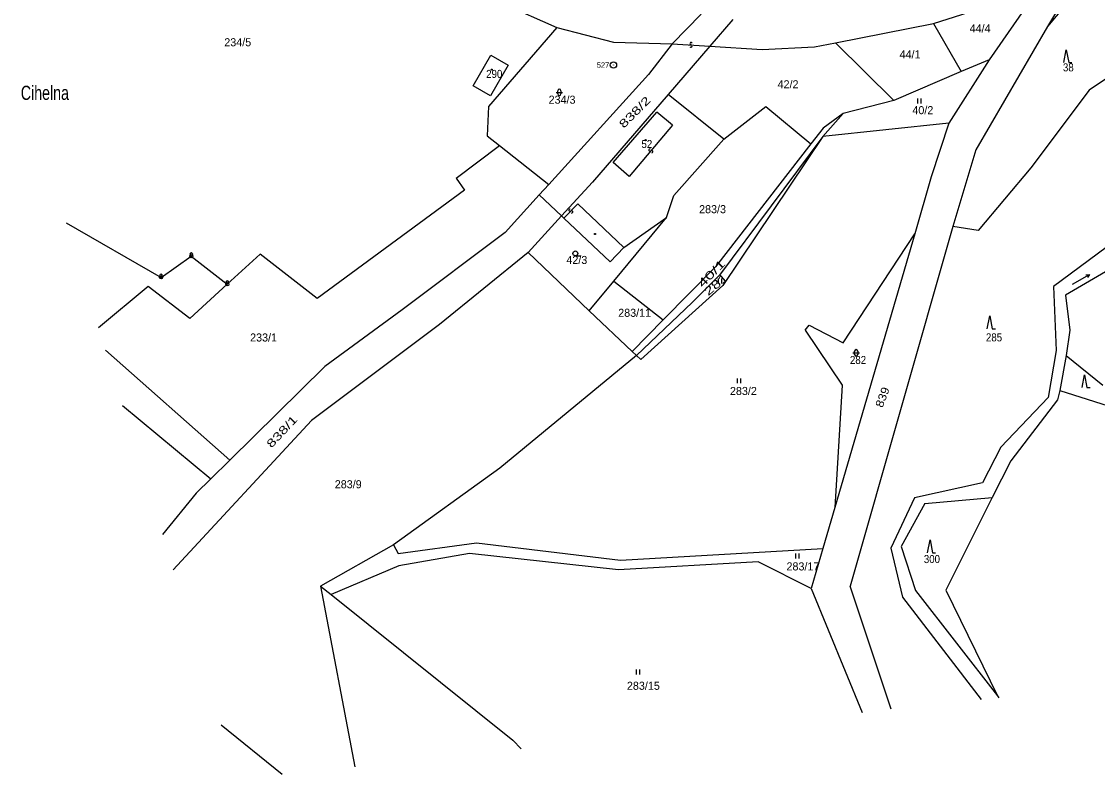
# Model space of a CAD drawing. Extents: x -680102 to -677253, y -1007548 to -1006096.
# Drawn here: x -680091.3 to -679757, y -1007547.6 to -1007313.8 of the extents above; entities that cross this region are included whole.
import ezdxf
from ezdxf.enums import TextEntityAlignment as Align

# ---------------------------------------------------------------- set-up
doc = ezdxf.new("R2010")
doc.units = 0
for name, color, linetype, lineweight in [('1', 7, 'Continuous', 25), ('24', 7, 'Continuous', 25), ('25', 7, 'Continuous', 25), ('4', 7, 'Continuous', 25)]:
    doc.layers.add(name, color=color, linetype=linetype, lineweight=lineweight)
for name, color, linetype in [('15', 7, 'Continuous'), ('17', 7, 'Continuous'), ('18', 7, 'Continuous'), ('19', 7, 'Continuous')]:
    doc.layers.add(name, color=color, linetype=linetype)

msp = doc.modelspace()

# ---------------------------------------------------------------- linework, layer by layer
at = {"layer": '1'}
for p, q in [((-679751.31, -1007289.93), (-679772.5, -1007315.36)), ((-679760.1, -1007294.19), (-679772.5, -1007315.36)), ((-679773.27, -1007300.56), (-679790.71, -1007325.72)), ((-679807.93, -1007314.43), (-679790.35, -1007308.83)), ((-679807.93, -1007314.43), (-679799.34, -1007329.39)), ((-679772.5, -1007315.36), (-679794.82, -1007353.69)), ((-679907.39, -1007320.2), (-679889.19, -1007320.71)), ((-679820.32, -1007338.31), (-679838.38, -1007320.42)), ((-679877.41, -1007321.47), (-679861.24, -1007322.51)), ((-679861.24, -1007322.51), (-679844.91, -1007321.71)), ((-679790.71, -1007325.72), (-679803.18, -1007345.43)), ((-679896.47, -1007330.3), (-679927.47, -1007364.41)), ((-679890.39, -1007336.48), (-679913.92, -1007363.71)), ((-679873.12, -1007350.39), (-679890.39, -1007336.48)), ((-679860.01, -1007340.18), (-679846.02, -1007351.79)), ((-679820.32, -1007338.31), (-679835.98, -1007342.4)), ((-679835.98, -1007342.4), (-679842.38, -1007349.53)), ((-679835.98, -1007342.4), (-679842.26, -1007346.96)), ((-679803.18, -1007345.43), (-679808.67, -1007362.08)), ((-679842.38, -1007349.53), (-679873.43, -1007395.77)), ((-679956.29, -1007362.46), (-679942.75, -1007352.36)), ((-679794.82, -1007353.69), (-679801.97, -1007377.5)), ((-679777.7, -1007359.21), (-679794.04, -1007378.71)), ((-679956.29, -1007362.46), (-679953.63, -1007366.19)), ((-679953.63, -1007366.19), (-679999.47, -1007399.87)), ((-679930.44, -1007367.67), (-679923.49, -1007374.2)), ((-679923.49, -1007374.2), (-679922.76, -1007374.88)), ((-679922.76, -1007374.88), (-679908.36, -1007388.4)), ((-679904.18, -1007383.99), (-679890.88, -1007374.63)), ((-679835.99, -1007413.54), (-679813.81, -1007379.71)), ((-679801.97, -1007377.5), (-679833.81, -1007489.16)), ((-679794.04, -1007378.71), (-679801.97, -1007377.5)), ((-680038.53, -1007386.69), (-680027.35, -1007395.38)), ((-679999.47, -1007399.87), (-680017.1, -1007386.06)), ((-679933.87, -1007385.58), (-679914.93, -1007403.62)), ((-679904.18, -1007383.99), (-679908.36, -1007388.4)), ((-679875.68, -1007389.94), (-679891.9, -1007406.43)), ((-680051.95, -1007396.06), (-680067.33, -1007408.97)), ((-680039.02, -1007406), (-680051.95, -1007396.06)), ((-679907.32, -1007394.45), (-679891.9, -1007406.43)), ((-679873.43, -1007395.77), (-679898.89, -1007418.79)), ((-679914.93, -1007403.62), (-679901.56, -1007416.26)), ((-679891.9, -1007406.43), (-679901.56, -1007416.26)), ((-680065.2, -1007415.89), (-680026.59, -1007450.04)), ((-679901.56, -1007416.26), (-679900.22, -1007417.53)), ((-679900.22, -1007417.53), (-679898.89, -1007418.79)), ((-679766.75, -1007417.51), (-679768.72, -1007428.41)), ((-679766.75, -1007417.51), (-679755.37, -1007426.71)), ((-679768.72, -1007428.41), (-679769.48, -1007431.29)), ((-679768.72, -1007428.41), (-679731.53, -1007440.19)), ((-680059.91, -1007432.99), (-680032.49, -1007455.85)), ((-679769.48, -1007431.29), (-679783.96, -1007450.17)), ((-680032.49, -1007455.85), (-680037.01, -1007460.3)), ((-680037.01, -1007460.3), (-680047.53, -1007473.06)), ((-679813.86, -1007461.69), (-679821.18, -1007477.36)), ((-679810.68, -1007463.44), (-679789.76, -1007461.61)), ((-679821.18, -1007477.36), (-679817.59, -1007492.51)), ((-679974.09, -1007482.85), (-679995.13, -1007491.74)), ((-679998.41, -1007489.12), (-679987.71, -1007545.18)), ((-679845.93, -1007489.86), (-679830.1, -1007528.31)), ((-679821.11, -1007527.35), (-679833.81, -1007489.16)), ((-679804.09, -1007490.35), (-679788.08, -1007523.17)), ((-679817.59, -1007492.51), (-679793.17, -1007524.36)), ((-680010.27, -1007547.6), (-680029.24, -1007532.26)), ((-679938.63, -1007536.9), (-679936.1, -1007539.66))]:
    msp.add_line(p, q, dxfattribs=at)
for points in [[(-680046.12, -1007230.11), (-680058.82, -1007235.88), (-680050.85, -1007238.38), (-679958.75, -1007300.67), (-679925.02, -1007315.68), (-679907.39, -1007320.2)], [(-679724.02, -1007294.07), (-679738.68, -1007321.18), (-679759.61, -1007335.18), (-679777.7, -1007359.21)], [(-679880.16, -1007311.59), (-679889.19, -1007320.71), (-679896.47, -1007330.3)], [(-679870.28, -1007313.22), (-679877.41, -1007321.47), (-679890.39, -1007336.48)], [(-679925.02, -1007315.68), (-679946.2, -1007340.16), (-679946.64, -1007349.3)], [(-679844.91, -1007321.71), (-679838.38, -1007320.42), (-679807.93, -1007314.43)], [(-679790.71, -1007325.72), (-679799.34, -1007329.39), (-679820.32, -1007338.31)], [(-679890.88, -1007374.63), (-679888.6, -1007367.89), (-679873.12, -1007350.39), (-679860.01, -1007340.18)], [(-679803.18, -1007345.43), (-679842.38, -1007349.53), (-679874.4, -1007392.57), (-679882.91, -1007401.06)], [(-679842.26, -1007346.96), (-679846.02, -1007351.79), (-679875.68, -1007389.94)], [(-679730.09, -1007346.1), (-679751.49, -1007381.96), (-679770.73, -1007396.14)], [(-679946.64, -1007349.3), (-679942.75, -1007352.36), (-679927.47, -1007364.41)], [(-679913.92, -1007363.71), (-679923.49, -1007374.2), (-679933.87, -1007385.58)], [(-679808.67, -1007362.08), (-679813.81, -1007379.71), (-679838.59, -1007464.68)], [(-679927.47, -1007364.41), (-679930.44, -1007367.67), (-679941.01, -1007379.3)], [(-679739.39, -1007369.2), (-679741.02, -1007375.78), (-679747.12, -1007387.18), (-679766.95, -1007398.78)], [(-680077.42, -1007376.32), (-680047.93, -1007393.26), (-680038.53, -1007386.69)], [(-679914.93, -1007403.62), (-679907.32, -1007394.45), (-679890.88, -1007374.63)], [(-679941.01, -1007379.3), (-679973.04, -1007403.34), (-679997.01, -1007420.92)], [(-679933.87, -1007385.58), (-679961.46, -1007407.85), (-680001.21, -1007437.68), (-680044.13, -1007484.09)], [(-680017.1, -1007386.06), (-680027.35, -1007395.38), (-680039.02, -1007406)], [(-679770.73, -1007396.14), (-679769.82, -1007416.01), (-679772.36, -1007430.54), (-679787.01, -1007446.01)], [(-679766.95, -1007398.78), (-679765.63, -1007409.67), (-679766.75, -1007417.51)], [(-679882.91, -1007401.06), (-679900.22, -1007417.53), (-679942.7, -1007452.46), (-679975.71, -1007476.35), (-679998.41, -1007489.12)], [(-679847.88, -1007409.63), (-679846.55, -1007408.12), (-679835.99, -1007413.54)], [(-679847.88, -1007409.63), (-679836.34, -1007426.77), (-679838.59, -1007464.68)], [(-679997.01, -1007420.92), (-680026.59, -1007450.04), (-680032.49, -1007455.85)], [(-679787.01, -1007446.01), (-679792.79, -1007457.04), (-679813.86, -1007461.69)], [(-679783.96, -1007450.17), (-679789.76, -1007461.61), (-679804.09, -1007490.35)], [(-679810.68, -1007463.44), (-679818, -1007476.86), (-679813.53, -1007490.48)], [(-679838.59, -1007464.68), (-679842.32, -1007477.47), (-679845.93, -1007489.86)], [(-679975.71, -1007476.35), (-679974.29, -1007478.98), (-679949.89, -1007475.73), (-679905.16, -1007481.02), (-679842.32, -1007477.47)], [(-679845.93, -1007489.86), (-679862.46, -1007481.63), (-679905.77, -1007484.07), (-679952.13, -1007478.98), (-679974.09, -1007482.85)], [(-679998.41, -1007489.12), (-679995.13, -1007491.74), (-679938.63, -1007536.9)], [(-679813.53, -1007490.48), (-679788.08, -1007523.17), (-679787.65, -1007523.77)]]:
    msp.add_lwpolyline(points, dxfattribs=at)
msp.add_lwpolyline([(-679945.53, -1007324.24), (-679940.08, -1007327.36), (-679945.55, -1007336.93), (-679951, -1007333.84)], close=True, dxfattribs=at)
at = {"layer": '24'}
for centre, radius in [((-679907.39, -1007327.33), 1), ((-679907.39, -1007327.33), 0.032), ((-680038.53, -1007386.69), 0.5), ((-680038.53, -1007386.69), 0.022), ((-680047.93, -1007393.26), 0.5), ((-680047.93, -1007393.26), 0.022), ((-680027.35, -1007395.38), 0.5), ((-680027.35, -1007395.38), 0.022)]:
    msp.add_circle(centre, radius, dxfattribs=at)
for centre in [(-680038.531, -1007386.127), (-680047.931, -1007392.697), (-680027.351, -1007394.817)]:
    msp.add_arc(centre, 0.437, 328.35109, 209.97456, dxfattribs=at)
at = {"layer": '25'}
for p, q in [((-679925.21, -1007335.82), (-679923.21, -1007335.82)), ((-679924.71, -1007336.32), (-679924.71, -1007335.32)), ((-679923.71, -1007335.32), (-679923.71, -1007336.32)), ((-679812.837, -1007339.255), (-679812.837, -1007337.755)), ((-679811.803, -1007339.255), (-679811.803, -1007337.755)), ((-679919.22, -1007386.57), (-679917.47, -1007386.57)), ((-679874.737, -1007395.155), (-679874.737, -1007393.655)), ((-679873.703, -1007395.155), (-679873.703, -1007393.655)), ((-679764.731, -1007395.347), (-679759.509, -1007392.393)), ((-679832.99, -1007416.69), (-679830.99, -1007416.69)), ((-679832.49, -1007417.19), (-679832.49, -1007416.19)), ((-679831.49, -1007416.19), (-679831.49, -1007417.19)), ((-679868.827, -1007426.125), (-679868.827, -1007424.625)), ((-679867.793, -1007426.125), (-679867.793, -1007424.625)), ((-679850.727, -1007480.525), (-679850.727, -1007479.025)), ((-679849.693, -1007480.525), (-679849.693, -1007479.025)), ((-679900.177, -1007516.555), (-679900.177, -1007515.055)), ((-679899.143, -1007516.555), (-679899.143, -1007515.055))]:
    msp.add_line(p, q, dxfattribs=at)
for points in [[(-679767.46, -1007326.58), (-679766.71, -1007322.58), (-679765.96, -1007326.58), (-679764.96, -1007326.58)], [(-679760.626, -1007392.45), (-679759.509, -1007392.393), (-679760.134, -1007393.321)], [(-679791.24, -1007409.19), (-679790.49, -1007405.19), (-679789.74, -1007409.19), (-679788.74, -1007409.19)], [(-679761.79, -1007427.47), (-679761.04, -1007423.47), (-679760.29, -1007427.47), (-679759.29, -1007427.47)], [(-679809.79, -1007478.75), (-679809.04, -1007474.75), (-679808.29, -1007478.75), (-679807.29, -1007478.75)]]:
    msp.add_lwpolyline(points, dxfattribs=at)
for centre, radius in [((-679945.2, -1007328.77), 0.175), ((-679897.4, -1007350.66), 0.175), ((-679913.11, -1007379.79), 0.175), ((-679919.22, -1007385.82), 0.75)]:
    msp.add_circle(centre, radius, dxfattribs=at)
for centre, radius, start, end in [((-679883.274, -1007320.724), 0.367, 33.69089, 265.93875), ((-679883.328, -1007321.457), 0.368, 213.8212, 85.8823), ((-679924.21, -1007335.32), 0.5, 0.101, 180.00143), ((-679924.21, -1007336.32), 0.5, 180.10243, 0.00286), ((-679896.048, -1007353.728), 0.369, 87.04511, 318.96286), ((-679895.491, -1007354.21), 0.368, 266.49438, 139.29849), ((-679920.893, -1007372.403), 0.367, 83.38608, 315.66359), ((-679920.368, -1007372.919), 0.369, 263.45581, 135.69015), ((-679831.99, -1007416.19), 0.5, 0.101, 180.00143), ((-679831.99, -1007417.19), 0.5, 180.10243, 0.00286)]:
    msp.add_arc(centre, radius, start, end, dxfattribs=at)
at = {"layer": '4'}
for p, q in [((-679889.19, -1007320.71), (-679877.41, -1007321.47)), ((-679907.43, -1007357.64), (-679893.87, -1007341.94)), ((-679889.03, -1007346.04), (-679893.87, -1007341.94))]:
    msp.add_line(p, q, dxfattribs=at)
for points in [[(-679889.03, -1007346.04), (-679902.5, -1007361.9), (-679907.43, -1007357.64)], [(-679922.76, -1007374.88), (-679918.5, -1007370.44), (-679904.18, -1007383.99)]]:
    msp.add_lwpolyline(points, dxfattribs=at)

# ---------------------------------------------------------------- texts
at = {"layer": '15', "width": 0.75}
msp.add_text('Cihelna', height=4.4, dxfattribs=at).set_placement((-680084.02, -1007338.16), align=Align.CENTER)
at = {"layer": '17', "width": 0.9}
msp.add_text('527', height=1.7, dxfattribs=at).set_placement((-679908.69, -1007328.18), align=Align.RIGHT)
at = {"layer": '18'}
for s, p in [('44/4', (-679796.75, -1007317.22)), ('234/5', (-680028.29, -1007321.51)), ('44/1', (-679818.5, -1007325.27)), ('42/2', (-679856.41, -1007334.56)), ('234/3', (-679927.54, -1007339.34)), ('40/2', (-679814.53, -1007342.6)), ('283/3', (-679880.79, -1007373.34)), ('42/3', (-679922.02, -1007389.1)), ('283/11', (-679905.92, -1007405.51)), ('233/1', (-680020.27, -1007413.17)), ('283/2', (-679871.2, -1007429.78)), ('283/9', (-679993.97, -1007458.74)), ('283/17', (-679853.63, -1007484.25)), ('283/15', (-679903.21, -1007521.31))]:
    msp.add_text(s, height=2.5, dxfattribs=at).set_placement(p)
at = {"layer": '18', "width": 0.9}
for s, p in [('38', (-679767.75, -1007329.31)), ('285', (-679791.67, -1007413.14)), ('282', (-679833.92, -1007420.16)), ('300', (-679810.97, -1007481.96))]:
    msp.add_text(s, height=2.5, dxfattribs=at).set_placement(p)
at = {"layer": '18', "width": 1.45}
msp.add_text('838/2', height=2.5, rotation=45, dxfattribs=at).set_placement((-679899.896, -1007342.843), align=Align.CENTER)
at = {"layer": '18'}
for s, rotation, width, p in [('40/1', 45, 1.6, (-679879.74, -1007396.628)), ('281', 40.4, 1.5, (-679877.928, -1007399.109)), ('839', 69.401, 1.15, (-679823.796, -1007433.903)), ('838/1', 46.9, 1.45, (-680013.629, -1007446.418))]:
    msp.add_text(s, height=2.5, rotation=rotation, dxfattribs=dict(at, width=width)).set_placement(p)
at = {"layer": '19', "width": 0.9}
for s, p in [('290', (-679946.93, -1007331.34)), ('52', (-679898.69, -1007353.1))]:
    msp.add_text(s, height=2.5, dxfattribs=at).set_placement(p)

doc.saveas('drawing.dxf')
